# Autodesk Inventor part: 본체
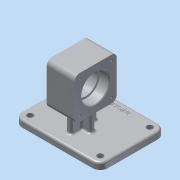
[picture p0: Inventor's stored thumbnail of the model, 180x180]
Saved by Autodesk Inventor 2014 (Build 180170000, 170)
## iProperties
Created: 2020-11
Part Number: 본체
Material: 알루미늄 6061
Document SubType Name: Modeling
Designer: kh
Density: 2.71 g/cm^3
Appearance: 알루미늄 - 평지
Mass: 711.128 g
Surface Area: 552.419 cm^2
Volume: 262.409 cm^3
Author: kh
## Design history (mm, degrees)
sketch "스케치1"
  geometry: L1 (-65, -49.5)-(65, -49.5); L2 (65, -49.5)-(65, 49.5); L3 (65, 49.5)-(-65, 49.5); L4 (-65, 49.5)-(-65, -49.5); L5 (-65, -49.5)-(65, 49.5); L6 (65, -49.5)-(-65, 49.5); 1 further point
  constraints: 12 end point, 2 midpoint, 2 parallel, 1 horizontal, 1 perpendicular
  dimensions: "d0" = 130 distance of L2.end L3.end; "d1" = 99 distance of L1.end L2.end
extrude "돌출1" new body sketch "스케치1" distance "d2" = 10; taper "d3" = 0 deg
fillet "모깎기1" dims "d4" = 12
sketch "스케치2"
  geometry: L1 (-53, -49.5)-(53, -49.5) reference; L2 (65, -37.5)-(65, 37.5) reference; L3 (53, 49.5)-(-53, 49.5) reference; L4 (4, -32.5)-(-4, -32.5); L5 (-4, -32.5)-(-4, 7.5); L6 (-4, 7.5)-(4, 7.5); L7 (4, 7.5)-(4, -32.5); L8 (0, -32.5)-(0, 7.5); L9 (17, -16.5)-(-17, -16.5); L10 (-17, -16.5)-(-17, -8.5); L11 (-17, -8.5)-(17, -8.5); L12 (17, -8.5)-(17, -16.5); L13 (-4, -12.5)-(4, -12.5); L14 (-17, -12.5)-(17, -12.5); 3 further points
  constraints: 22 end point, 8 midpoint, 4 parallel, 2 horizontal, 2 perpendicular, 1 vertical alignment
  dimensions: "d6" = 8 distance of L5.end L6.end; "d8" = 65 distance between parallel lines of L2 L8; "d10" = 34 distance of L9.start L9.end; "d11" = 8 distance of L11.end L9.start; "d12" = 40 distance of L6.end L4.start; "d13" = 62 distance between parallel lines of L13 L3; "d14" = 62 distance between parallel lines of L14 L3
extrude "돌출2" join sketch "스케치2" distance "d15" = 60; taper "d16" = 0 deg
sketch "스케치3"
  geometry: L1 (-16.5, 70)-(-32.5, 70) reference; L2 (7.5, 70)-(-8.5, 70) reference; L3 (-8.5, 70)-(-16.5, 70) reference; L4 (-44.5, 38)-(19.5, 38); L5 (19.5, 38)-(19.5, 102); L6 (19.5, 102)-(-44.5, 102); L7 (-44.5, 102)-(-44.5, 38); L8 (-44.5, 38)-(19.5, 102); L9 (19.5, 38)-(-44.5, 102); 2 further points
  constraints: 12 end point, 3 midpoint, 2 parallel, 1 horizontal, 1 perpendicular
  dimensions: "d17" = 64 distance of L4.end L5.end; "d18" = 64 distance of L5.end L6.end
extrude "돌출3" join sketch "스케치3" stored distance "d19" = 42; taper "d20" = 0 deg
fillet "모깎기2" dims "d21" = 8
sketch "스케치4"
  geometry: L1 (-46, 19.5)-(-94, 19.5) reference; L2 (-102, 11.5)-(-102, -36.5) reference; L3 (-94, -44.5)-(-46, -44.5) reference; L4 (-38, -36.5)-(-38, 11.5) reference; L5 (-102, -12.5)-(-38, -12.5); L6 (-70, 19.5)-(-70, -44.5); C1 r 21 at (-70, -12.5); 1 further point
  constraints: 5 midpoint, 4 end point, 1 centre point
  dimensions: "d22" = 42 diameter of C1
extrude "돌출4" cut sketch "스케치4" distance "d23" = 15; taper "d24" = 0 deg
sketch "스케치5"
  geometry: C1 r 21 at (0, 0) reference; C2 r 18 at (0, 0); 1 further point
  constraints: 1 centre point, 1 coincident
  dimensions: "d25" = 36 diameter of C2
extrude "돌출5" cut sketch "스케치5" distance "d26" = 15; taper "d27" = 0 deg
sketch "스케치6"
  geometry: A1 r 8 centre (-46, 11.5) between (-38, 11.5) and (-46, 19.5) reference; A2 r 8 centre (-94, 11.5) between (-94, 19.5) and (-102, 11.5) reference; A3 r 8 centre (-94, -36.5) between (-102, -36.5) and (-94, -44.5) reference; A4 r 8 centre (-46, -36.5) between (-46, -44.5) and (-38, -36.5) reference; 3 further points
  dimensions: "d54" = 48 distance of point (-46, -36.5) A3.centre; "d55" = 48 distance of point (-46, 11.5) A2.centre
hole "구멍1" sketch "스케치6" diameter "d28" = 3.242; stored, may be unused: countersink angle "d32" = 90 deg, drill point angle "d34" = 118 deg; dims "d29" = 8, "d30" = 4, "d31" = 2, "d33" = 10
sketch "스케치7"
  geometry: A1 r 12 centre (-53, -37.5) between (-65, -37.5) and (-53, -49.5) reference; A2 r 12 centre (53, -37.5) between (53, -49.5) and (65, -37.5) reference; A3 r 12 centre (53, 37.5) between (65, 37.5) and (53, 49.5) reference; A4 r 12 centre (-53, 37.5) between (-53, 49.5) and (-65, 37.5) reference; 1 further point
hole "구멍2" sketch "스케치7" at (53, 37.5), (53, -37.5), (-53, -37.5), (-53, 37.5) diameter "d35" = 9; stored, may be unused: countersink angle "d39" = 90 deg, drill point angle "d41" = 0 deg; dims "d36" = 8, "d37" = 4, "d38" = 2, "d40" = 10
fillet "모깎기3" dims "d42" = 3
fillet "모깎기4" dims "d43" = 3
fillet "모깎기5" dims "d44" = 3
fillet "모깎기6" dims "d45" = 0.3
node "작업 평면1"
sketch "스케치8"
  geometry: L1 (53, 49.5)-(-53, 49.5) reference; L2 (-65, 37.5)-(-65, -37.5) reference; L3 (65, -37.5)-(65, 37.5) reference; 2 further points
  constraints: 1 other
  dimensions: "d47" = 10 distance from line of L1 point (0, 39.5); "d48" = 65 distance from line of L3 point (0, 39.5)
feature "엠보싱1" sketch "스케치8" dims "d0" = 130, "d1" = 99, "d6" = 8, "d8" = 65, "d12" = 40, "d13" = 62, "d49" = 0.5, "d50" = 0
chamfer "모따기1" distance "d51" = 1; stored, may be unused: second distance "d52" = 2, angle "d53" = 45 deg
node "솔리드1"
mirror "대칭1"
mirror "대칭2"
